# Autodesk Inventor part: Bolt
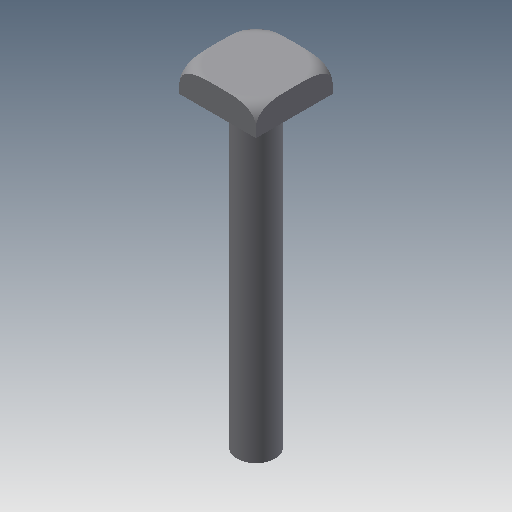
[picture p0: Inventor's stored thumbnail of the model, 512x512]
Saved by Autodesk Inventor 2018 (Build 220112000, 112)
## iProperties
Created: 2009-04
Part Number: Bolt
Document SubType Name: Modeling
Designer: Sham
Density: 1 g/cm^3
Material: Generic
Appearance: Default
Mass: 15.4123 g
Surface Area: 54.8695 cm^2
Volume: 15.4123 cm^3
Author: Sham
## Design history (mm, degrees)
sketch "Sketch1"
  geometry: L1 (-12, 12)-(12, 12); L2 (12, 12)-(12, -12); L3 (12, -12)-(-12, -12); L4 (-12, -12)-(-12, 12); 1 further point
  constraints: 8 end point, 2 parallel, 2 perpendicular, 1 horizontal, 1 other
  dimensions: "d0" = 24 distance of L1.start L1.end; "d1" = 12 distance from line of L2 point (0, 0); "d2" = 12 distance from line of L1 point (0, 0)
extrude "Extrusion1" new body sketch "Sketch1" distance "d3" = 8; taper "d4" = 0 deg
sketch "Sketch2"
  geometry: C1 r 6 at (0, 0)
  constraints: 1 centre point
  dimensions: "d5" = 12 diameter of C1
extrude "Extrusion2" join sketch "Sketch2" distance "d6" = 96; taper "d7" = 0 deg
workpoint "Work Point1"
workplane "Work Plane1"
sketch "Sketch3"
  geometry: L1 (33.941, 5)-(33.941, 6); L2 (28.941, 0)-(28.405, 0); L3 (16.971, 125.007)-(16.971, -22.043) reference; A1 r 5 centre (28.941, 5) between (28.941, 0) and (33.941, 5); 1 further point
  constraints: 4 end point, 2 point on circle, 2 point on line, 2 tangent, 1 centre point, 1 perpendicular
  dimensions: "d10" = 5 radius of A1
revolve "Revolution1" sketch "Sketch3" stored, may be unused: angle "d12" = 90 deg
body "Solid1"
other parameters: "d11" = 90 deg
